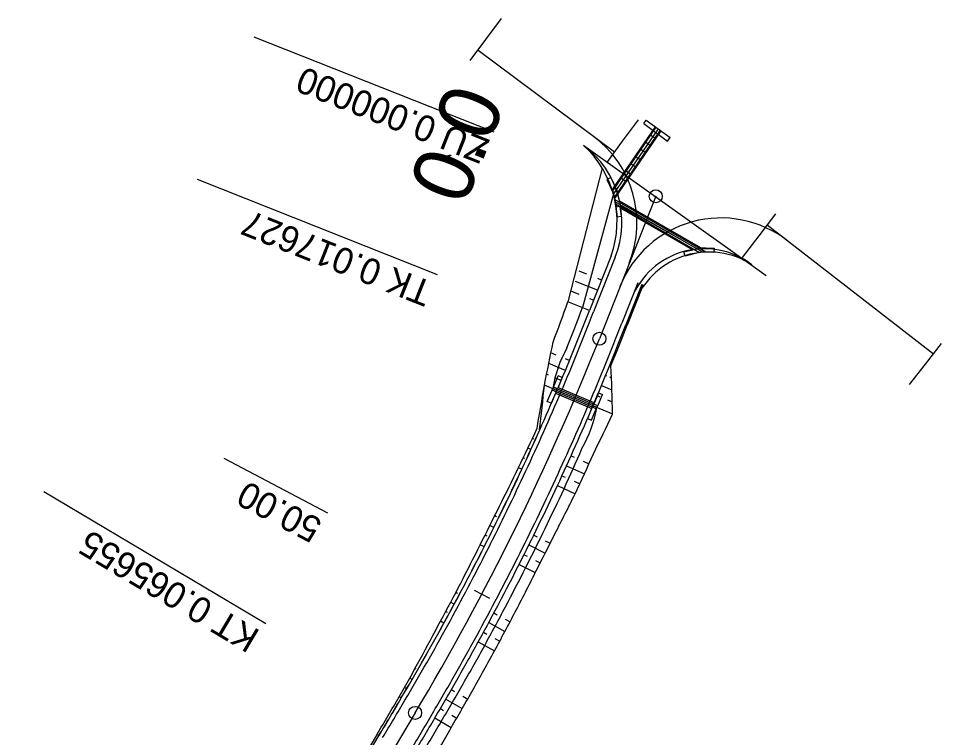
# Model space of a CAD drawing. Extents: x -481645 to -478728, y -1113199 to -1110710.
# Drawn here: x -479519.7 to -479413.6, y -1112428.2 to -1112345.5 of the extents above; entities that cross this region are included whole.
import ezdxf

# ---------------------------------------------------------------- set-up
doc = ezdxf.new("R2010")
doc.units = 0
for name, color, linetype in [('CP14_HRANA_TELESO', 7, 'Continuous'), ('CP14_KORUNA', 7, 'Continuous'), ('CP14_OSA', 7, 'Continuous'), ('CP14_PRIKOP', 7, 'Continuous'), ('CP14_STANICENI', 7, 'Continuous'), ('CP14_VOZOVKA', 7, 'Continuous'), ('CP14_ZPEVKRAJ', 7, 'Continuous'), ('CP1_HATCH_SLOPE_L', 7, 'Continuous'), ('CP1_HATCH_SLOPE_R', 7, 'Continuous'), ('CP1_HLBODY', 7, 'Continuous'), ('CP1_HRANA_TELESO', 7, 'Continuous'), ('CP1_OSA', 7, 'Continuous'), ('CP1_STANICENI', 7, 'Continuous'), ('CP1_VOZOVKA', 7, 'Continuous'), ('CP1_ZPEVKRAJ', 7, 'Continuous')]:
    doc.layers.add(name, color=color, linetype=linetype)

# ---------------------------------------------------------------- blocks, each defined once
blk = doc.blocks.new('A$C716')
at = {"layer": 'CP14_ZPEVKRAJ'}
for p, q in [((-5.015, 2.333), (-4.471, 3.623)), ((-4.01, 3.428), (-4.554, 2.138)), ((-4.01, 3.428), (-4.471, 3.623)), ((-5.17, 1.964), (-5.015, 2.333)), ((0, 0), (-5.093, 2.148)), ((-5.015, 2.333), (-0.383, 0.379)), ((-4.554, 2.138), (-5.015, 2.333)), ((-0.325, 0.517), (-4.496, 2.277)), ((-5.715, 0.674), (-5.17, 1.964)), ((-4.71, 1.77), (-5.254, 0.48)), ((-0.078, -0.184), (-5.171, 1.964)), ((-4.71, 1.77), (-5.17, 1.964)), ((-4.768, 1.632), (-0.597, -0.128)), ((0.161, 1.669), (-0.383, 0.379)), ((0.078, 0.184), (0.622, 1.474)), ((0.161, 1.669), (0.622, 1.474)), ((-5.254, 0.48), (-5.715, 0.674)), ((-0.538, 0.01), (-1.083, -1.28)), ((-0.078, -0.184), (-0.999, 0.204)), ((0.078, 0.184), (-0.844, 0.573)), ((-0.538, 0.01), (-0.383, 0.379)), ((-0.078, -0.184), (0.078, 0.184)), ((-0.622, -1.474), (-0.078, -0.184)), ((-1.083, -1.28), (-0.622, -1.474))]:
    blk.add_line(p, q, dxfattribs=at)

msp = doc.modelspace()

# ---------------------------------------------------------------- linework, layer by layer
at = {"layer": 'CP14_HRANA_TELESO'}
for p, q in [((-479448.47, -1112377.27), (-479448.47, -1112377.27)), ((-479448.4, -1112377.29), (-479448.34, -1112377.32)), ((-479448.93, -1112378.43), (-479448.8, -1112378.48)), ((-479449.39, -1112379.59), (-479449.39, -1112379.59)), ((-479449.32, -1112379.62), (-479449.26, -1112379.64)), ((-479449.85, -1112380.75), (-479449.72, -1112380.81)), ((-479452.19, -1112386.58), (-479452.08, -1112386.62)), ((-479451.75, -1112386.76), (-479451.52, -1112386.85)), ((-479452.67, -1112387.75), (-479451.47, -1112388.24)), ((-479453.15, -1112388.91), (-479452.85, -1112389.04)), ((-479451.98, -1112389.4), (-479451.43, -1112389.63)), ((-479453.64, -1112390.07), (-479451.39, -1112391.02)), ((-479456.17, -1112395.84), (-479455.8, -1112396)), ((-479454.77, -1112396.47), (-479454.11, -1112396.76)), ((-479456.69, -1112396.98), (-479454.63, -1112397.92)), ((-479457.21, -1112398.13), (-479456.83, -1112398.3)), ((-479455.81, -1112398.77), (-479455.16, -1112399.07)), ((-479457.74, -1112399.27), (-479455.7, -1112400.22)), ((-479460.45, -1112404.95), (-479460.08, -1112405.14)), ((-479461.01, -1112406.08), (-479459.13, -1112407.02)), ((-479459.13, -1112405.6), (-479458.56, -1112405.89)), ((-479461.57, -1112407.21), (-479461.2, -1112407.4)), ((-479462.14, -1112408.34), (-479460.28, -1112409.28)), ((-479460.26, -1112407.87), (-479459.7, -1112408.15)), ((-479465.04, -1112413.92), (-479464.67, -1112414.12)), ((-479463.74, -1112414.62), (-479463.17, -1112414.92)), ((-479465.63, -1112415.03), (-479463.77, -1112416.04)), ((-479466.23, -1112416.14), (-479465.86, -1112416.34)), ((-479464.93, -1112416.85), (-479464.36, -1112417.16)), ((-479466.84, -1112417.25), (-479464.97, -1112418.27)), ((-479469.92, -1112422.74), (-479469.56, -1112422.95)), ((-479470.55, -1112423.83), (-479468.67, -1112424.92)), ((-479468.62, -1112423.49), (-479468.04, -1112423.82)), ((-479471.19, -1112424.91), (-479470.83, -1112425.12)), ((-479471.83, -1112426), (-479469.95, -1112427.11)), ((-479469.89, -1112425.68), (-479469.31, -1112426.02))]:
    msp.add_line(p, q, dxfattribs=at)
at = {"layer": 'CP14_KORUNA'}
for p, q in [((-479447.81, -1112357.6), (-479447.51, -1112357.2)), ((-479447.81, -1112357.6), (-479445.08, -1112359.63)), ((-479447.51, -1112357.2), (-479444.78, -1112359.22)), ((-479446.48, -1112357.97), (-479451.45, -1112365.21)), ((-479446.4, -1112358.02), (-479451.41, -1112365.33)), ((-479446.16, -1112358.2), (-479451.3, -1112365.7)), ((-479445.92, -1112358.38), (-479451.21, -1112366.1)), ((-479445.84, -1112358.44), (-479451.18, -1112366.24)), ((-479447.58, -1112359.74), (-479447.08, -1112360.08)), ((-479447.01, -1112358.91), (-479446.52, -1112359.25)), ((-479445.08, -1112359.63), (-479444.78, -1112359.22)), ((-479448.14, -1112360.56), (-479447.65, -1112360.9)), ((-479448.14, -1112360.56), (-479447.65, -1112360.9)), ((-479448.14, -1112360.56), (-479447.65, -1112360.9)), ((-479448.14, -1112360.56), (-479447.65, -1112360.9)), ((-479448.14, -1112360.56), (-479447.65, -1112360.9)), ((-479448.14, -1112360.56), (-479447.65, -1112360.9)), ((-479448.14, -1112360.56), (-479447.65, -1112360.9)), ((-479448.14, -1112360.56), (-479447.65, -1112360.9)), ((-479448.71, -1112361.39), (-479448.21, -1112361.73)), ((-479449.27, -1112362.21), (-479448.78, -1112362.55)), ((-479451.58, -1112363.83), (-479452.04, -1112364.03)), ((-479451.58, -1112363.83), (-479451.03, -1112365.08)), ((-479450.48, -1112363.81), (-479449.83, -1112364.26)), ((-479449.84, -1112363.04), (-479449.34, -1112363.38)), ((-479452.04, -1112364.03), (-479451.3, -1112365.7)), ((-479451.3, -1112365.7), (-479450.95, -1112367.24)), ((-479450.92, -1112365.14), (-479450.47, -1112367.13)), ((-479450.47, -1112367.13), (-479450.95, -1112367.24))]:
    msp.add_line(p, q, dxfattribs=at)
at = {"layer": 'CP14_OSA'}
msp.add_circle((-479446.42, -1112365.98), 0.75, dxfattribs=at)
at = {"layer": 'CP14_PRIKOP'}
for p, q in [((-479454.36, -1112374.93), (-479455.23, -1112374.59)), ((-479452.66, -1112375.61), (-479453.08, -1112375.44)), ((-479453.12, -1112376.77), (-479455.66, -1112375.77)), ((-479455.24, -1112377.27), (-479456.09, -1112376.94)), ((-479453.58, -1112377.93), (-479453.99, -1112377.77)), ((-479454.04, -1112379.1), (-479456.52, -1112378.11)), ((-479457.88, -1112384.25), (-479458.48, -1112384)), ((-479456.82, -1112386.02), (-479458.72, -1112385.23)), ((-479456.35, -1112384.87), (-479456.82, -1112384.68)), ((-479458.77, -1112386.55), (-479458.97, -1112386.46)), ((-479457.3, -1112387.17), (-479457.94, -1112386.9)), ((-479457.79, -1112388.31), (-479459.23, -1112387.69)), ((-479460.44, -1112393.91), (-479460.6, -1112393.84)), ((-479460.27, -1112393.99), (-479460.28, -1112393.99)), ((-479460.78, -1112395.12), (-479461.13, -1112394.96)), ((-479461.48, -1112396.16), (-479461.66, -1112396.08)), ((-479461.3, -1112396.25), (-479461.3, -1112396.25)), ((-479461.82, -1112397.38), (-479462.2, -1112397.2)), ((-479464.72, -1112402.86), (-479464.94, -1112402.75)), ((-479464.49, -1112402.97), (-479464.5, -1112402.97)), ((-479465.04, -1112404.08), (-479465.49, -1112403.86)), ((-479465.83, -1112405.08), (-479466.05, -1112404.97)), ((-479465.59, -1112405.2), (-479465.6, -1112405.19)), ((-479466.15, -1112406.3), (-479466.61, -1112406.07)), ((-479469.23, -1112411.69), (-479469.43, -1112411.58)), ((-479469.6, -1112412.9), (-479470.01, -1112412.68)), ((-479469.01, -1112411.81), (-479469.02, -1112411.81)), ((-479470.39, -1112413.88), (-479470.59, -1112413.77)), ((-479470.78, -1112415.08), (-479471.18, -1112414.86)), ((-479470.19, -1112413.99), (-479470.19, -1112413.99)), ((-479473.97, -1112420.4), (-479474.12, -1112420.32)), ((-479473.82, -1112420.49), (-479473.83, -1112420.49)), ((-479474.44, -1112421.56), (-479474.72, -1112421.4)), ((-479475.21, -1112422.55), (-479475.33, -1112422.48)), ((-479475.07, -1112422.63), (-479475.07, -1112422.63)), ((-479475.7, -1112423.7), (-479475.95, -1112423.55))]:
    msp.add_line(p, q, dxfattribs=at)
at = {"layer": 'CP14_STANICENI'}
msp.add_line((-479454.71, -1112360.13), (-479433.74, -1112375.08), dxfattribs=at)
for centre, radius, start, end in [((-479461.31, -1112368.94), 11, 338.3823, 53.171), ((-479462.72, -1112368.87), 11.85, 340.5708, 47.4974), ((-479440.81, -1112381.01), 9, 52.7737, 158.3823), ((-479440.32, -1112381.56), 9.17, 57.3103, 156.3307)]:
    msp.add_arc(centre, radius, start, end, dxfattribs=at)
at = {"layer": 'CP14_VOZOVKA'}
for p, q in [((-479465.96, -1112347.94), (-479464.16, -1112345.52)), ((-479467.75, -1112350.37), (-479465.96, -1112347.94)), ((-479466.85, -1112349.16), (-479451.15, -1112360.88)), ((-479450.23, -1112359.65), (-479448.4, -1112357.17)), ((-479452.06, -1112362.12), (-479450.23, -1112359.65)), ((-479450.48, -1112367.03), (-479443.11, -1112371.16)), ((-479432.67, -1112368.01), (-479434.57, -1112370.51)), ((-479433.62, -1112369.26), (-479414.48, -1112384.1)), ((-479434.57, -1112370.51), (-479436.47, -1112373.01)), ((-479415.39, -1112385.28), (-479413.56, -1112382.92)), ((-479417.23, -1112387.63), (-479415.39, -1112385.28))]:
    msp.add_line(p, q, dxfattribs=at)
for centre, start, end in [((-479461.09, -1112369.06), 338.3823, 53.2576), ((-479438.92, -1112380.97), 52.2213, 158.3823)]:
    msp.add_arc(centre, 12.5, start, end, dxfattribs=at)
at = {"layer": 'CP14_ZPEVKRAJ'}
for p, q in [((-479450.92, -1112365.07), (-479451.41, -1112365.18)), ((-479451.41, -1112365.18), (-479451.09, -1112366.61)), ((-479450.56, -1112366.69), (-479450.92, -1112365.07)), ((-479441.4, -1112371.98), (-479451.15, -1112366.35)), ((-479451.09, -1112366.61), (-479450.87, -1112368.34)), ((-479441.1, -1112372.38), (-479451.09, -1112366.61)), ((-479451.05, -1112366.86), (-479441.38, -1112372.45)), ((-479450.6, -1112366.49), (-479441.28, -1112371.87)), ((-479450.38, -1112368.28), (-479450.51, -1112367.18)), ((-479442.21, -1112372.15), (-479450.49, -1112367.36)), ((-479450.87, -1112368.34), (-479450.38, -1112368.28)), ((-479443.18, -1112372.38), (-479442, -1112372.09)), ((-479443.05, -1112372.87), (-479443.18, -1112372.38)), ((-479441.1, -1112372.38), (-479443.05, -1112372.87)), ((-479441.62, -1112371.85), (-479439.71, -1112371.96)), ((-479440.65, -1112372.41), (-479441.4, -1112371.98)), ((-479439.74, -1112372.46), (-479441.1, -1112372.38)), ((-479439.71, -1112371.96), (-479439.74, -1112372.46))]:
    msp.add_line(p, q, dxfattribs=at)
at = {"layer": 'CP1_HATCH_SLOPE_L'}
for p, q in [((-479484.13, -1112402.43), (-479496.07, -1112396.14)), ((-479467.32, -1112411.29), (-479465.55, -1112412.23))]:
    msp.add_line(p, q, dxfattribs=at)
at = {"layer": 'CP1_HATCH_SLOPE_R'}
for p, q in [((-479465.01, -1112358.61), (-479492.62, -1112347.67)), ((-479471.51, -1112375), (-479499.12, -1112364.06)), ((-479491.28, -1112415.18), (-479516.79, -1112399.97))]:
    msp.add_line(p, q, dxfattribs=at)
for centre in [(-479446.42, -1112365.98), (-479452.91, -1112382.37), (-479474.1, -1112425.41)]:
    msp.add_circle(centre, 0.75, dxfattribs=at)
at = {"layer": 'CP1_HLBODY'}
for p, q in [((-479451.73, -1112374.63), (-479453.57, -1112379.28)), ((-479448.48, -1112375.92), (-479450.32, -1112380.57))]:
    msp.add_line(p, q, dxfattribs=at)
for centre, radius, start, end in [((-480285.69, -1112050.41), 894.75, 338.11546, 338.43476), ((-480292.19, -1112047.81), 905.25, 338.11578, 338.43312), ((-479731.81, -1112271.84), 298.25, 336.9742, 337.9291), ((-479731.81, -1112271.84), 301.75, 336.9742, 337.9291), ((-479731.81, -1112271.84), 298.25, 336.0193, 336.9742), ((-479731.81, -1112271.84), 301.75, 336.0193, 336.9742), ((-479731.81, -1112271.84), 298.25, 335.0643, 336.0193), ((-479731.81, -1112271.84), 301.75, 335.0643, 336.0193), ((-479731.81, -1112271.84), 298.25, 334.1094, 335.0643), ((-479731.81, -1112271.84), 301.75, 334.1094, 335.0643), ((-479731.81, -1112271.84), 298.25, 333.1545, 334.1094), ((-479731.81, -1112271.84), 301.75, 333.1545, 334.1094), ((-479731.81, -1112271.84), 298.25, 332.1995, 333.1545), ((-479731.81, -1112271.84), 301.75, 332.1995, 333.1545), ((-479731.81, -1112271.84), 298.25, 331.2446, 332.1995), ((-479731.81, -1112271.84), 301.75, 331.2446, 332.1995), ((-479731.81, -1112271.84), 298.25, 330.2897, 331.2446), ((-479731.81, -1112271.84), 301.75, 330.2897, 331.2446), ((-479731.81, -1112271.84), 298.25, 329.3347, 330.2897), ((-479731.81, -1112271.84), 301.75, 329.3347, 330.2897), ((-479604.65, -1112349.8), 149.12, 328.2579, 330.1776), ((-479603.14, -1112350.69), 150.88, 328.2677, 330.168)]:
    msp.add_arc(centre, radius, start, end, dxfattribs=at)
at = {"layer": 'CP1_HRANA_TELESO'}
for p, q in [((-479452.57, -1112362.76), (-479456.52, -1112378.11)), ((-479447.88, -1112376.16), (-479449.72, -1112380.81)), ((-479478.48, -1112427.86), (-479481.04, -1112432.16))]:
    msp.add_line(p, q, dxfattribs=at)
for centre, radius, start, end in [((-480288.38, -1112074.21), 885.64, 339.60985, 339.93096), ((-480293.42, -1112047.43), 907.18, 338.12203, 338.43901), ((-479748.53, -1112326.52), 295.7, 348.0615, 349.0346), ((-479754.84, -1112398.59), 303.55, 1.4283, 2.4777), ((-479752.3, -1112340.85), 296.79, 349.9355, 350.9194), ((-479727.22, -1112261.78), 304.61, 333.9376, 334.8932), ((-479729.9, -1112267.71), 297.37, 334.187, 335.142), ((-479731.4, -1112270.94), 304.51, 334.878, 335.8329), ((-479729.78, -1112267.64), 297.29, 333.21, 334.1651), ((-479728.52, -1112265.13), 304.43, 332.7023, 333.6575), ((-479731.36, -1112270.93), 297.24, 332.9573, 333.9123), ((-479730.73, -1112269.68), 304.35, 332.698, 333.6529), ((-479732.66, -1112273.5), 297.25, 332.5591, 333.514), ((-479732.53, -1112273.24), 304.35, 332.495, 333.4499), ((-479732.63, -1112273.38), 297.28, 331.5798, 332.5348), ((-479732.53, -1112273.18), 304.37, 331.5291, 332.484), ((-479734.58, -1112276.91), 297.34, 331.4025, 332.3576), ((-479732.62, -1112273.3), 304.4, 330.6036, 331.5586), ((-479733.87, -1112275.44), 297.43, 330.1327, 331.0878), ((-479732.62, -1112273.24), 304.42, 329.6373, 330.5923), ((-479605.41, -1112350.35), 148.73, 328.5897, 330.5138), ((-479602.42, -1112352.13), 152.22, 328.6037, 330.4895)]:
    msp.add_arc(centre, radius, start, end, dxfattribs=at)
at = {"layer": 'CP1_OSA'}
for p, q in [((-479446.42, -1112365.98), (-479452.91, -1112382.37)), ((-479474.1, -1112425.41), (-479519.71, -1112501.96))]:
    msp.add_line(p, q, dxfattribs=at)
msp.add_arc((-479731.81, -1112271.84), 300, 329.2096, 338.3823, dxfattribs=at)
at = {"layer": 'CP1_STANICENI'}
for p, q in [((-479451.08, -1112372.99), (-479453.57, -1112379.28)), ((-479448.48, -1112375.92), (-479450.32, -1112380.57))]:
    msp.add_line(p, q, dxfattribs=at)
for centre, radius, start, end in [((-480285.69, -1112050.41), 894.75, 338.11546, 338.43476), ((-480292.19, -1112047.81), 905.25, 338.11578, 338.43312), ((-479731.81, -1112271.84), 298.25, 336.9742, 337.9291), ((-479731.81, -1112271.84), 301.75, 336.9742, 337.9291), ((-479731.81, -1112271.84), 298.25, 336.0193, 336.9742), ((-479731.81, -1112271.84), 301.75, 336.0193, 336.9742), ((-479731.81, -1112271.84), 298.25, 335.0643, 336.0193), ((-479731.81, -1112271.84), 301.75, 335.0643, 336.0193), ((-479731.81, -1112271.84), 298.25, 334.1094, 335.0643), ((-479731.81, -1112271.84), 301.75, 334.1094, 335.0643), ((-479731.81, -1112271.84), 298.25, 333.1545, 334.1094), ((-479731.81, -1112271.84), 301.75, 333.1545, 334.1094), ((-479731.81, -1112271.84), 298.25, 332.1995, 333.1545), ((-479731.81, -1112271.84), 301.75, 332.1995, 333.1545), ((-479731.81, -1112271.84), 298.25, 331.2446, 332.1995), ((-479731.81, -1112271.84), 301.75, 331.2446, 332.1995), ((-479731.81, -1112271.84), 298.25, 330.2897, 331.2446), ((-479731.81, -1112271.84), 301.75, 330.2897, 331.2446), ((-479731.81, -1112271.84), 298.25, 329.3347, 330.2897), ((-479731.81, -1112271.84), 301.75, 329.3347, 330.2897), ((-479604.65, -1112349.8), 149.12, 328.2579, 330.1776), ((-479603.14, -1112350.69), 150.88, 328.2677, 330.168)]:
    msp.add_arc(centre, radius, start, end, dxfattribs=at)
at = {"layer": 'CP1_VOZOVKA'}
for p, q in [((-479451.54, -1112372.81), (-479454.04, -1112379.1)), ((-479448.01, -1112376.11), (-479449.85, -1112380.75)), ((-479478.26, -1112427.99), (-479480.82, -1112432.29))]:
    msp.add_line(p, q, dxfattribs=at)
for centre, radius, start, end in [((-480284.76, -1112050.78), 893.25, 338.11542, 338.43499), ((-480293.12, -1112047.44), 906.75, 338.11583, 338.43289), ((-479731.81, -1112271.84), 297.75, 336.9742, 337.9291), ((-479731.81, -1112271.84), 302.25, 336.9742, 337.9291), ((-479731.81, -1112271.84), 297.75, 336.0193, 336.9742), ((-479731.81, -1112271.84), 302.25, 336.0193, 336.9742), ((-479731.81, -1112271.84), 297.75, 335.0643, 336.0193), ((-479731.81, -1112271.84), 302.25, 335.0643, 336.0193), ((-479731.81, -1112271.84), 297.75, 334.1094, 335.0643), ((-479731.81, -1112271.84), 302.25, 334.1094, 335.0643), ((-479731.81, -1112271.84), 297.75, 333.1545, 334.1094), ((-479731.81, -1112271.84), 302.25, 333.1545, 334.1094), ((-479731.81, -1112271.84), 297.75, 332.1995, 333.1545), ((-479731.81, -1112271.84), 302.25, 332.1995, 333.1545), ((-479731.81, -1112271.84), 297.75, 331.2446, 332.1995), ((-479731.81, -1112271.84), 302.25, 331.2446, 332.1995), ((-479731.81, -1112271.84), 297.75, 330.2897, 331.2446), ((-479731.81, -1112271.84), 302.25, 330.2897, 331.2446), ((-479731.81, -1112271.84), 297.75, 329.3347, 330.2897), ((-479731.81, -1112271.84), 302.25, 329.3347, 330.2897), ((-479604.86, -1112349.67), 148.88, 328.2565, 330.179), ((-479602.93, -1112350.82), 151.12, 328.2691, 330.1666)]:
    msp.add_arc(centre, radius, start, end, dxfattribs=at)
at = {"layer": 'CP1_ZPEVKRAJ'}
for p, q in [((-479451.3, -1112365.7), (-479454.85, -1112378.78)), ((-479448, -1112376.11), (-479449.85, -1112380.76)), ((-479478.27, -1112427.99), (-479480.82, -1112432.28))]:
    msp.add_line(p, q, dxfattribs=at)
for centre, radius, start, end in [((-480286.21, -1112058.91), 890.78, 338.63608, 338.95613), ((-480293.14, -1112047.43), 906.78, 338.11583, 338.43288), ((-479444.56, -1112390.23), 13.87, 150.585, 171.1801), ((-479754.79, -1112358.91), 296.96, 353.4357, 354.4366), ((-479468.8, -1112387.22), 15.91, 330.6869, 348.9826), ((-479731.81, -1112271.84), 297.74, 335.0643, 336.0193), ((-479732.87, -1112274.2), 303.07, 335.5529, 336.5079), ((-479731.81, -1112271.84), 297.74, 334.1094, 335.0643), ((-479731.81, -1112271.84), 303.09, 334.1094, 335.0643), ((-479731.81, -1112271.84), 297.74, 333.1545, 334.1094), ((-479731.81, -1112271.84), 303.09, 333.1545, 334.1094), ((-479731.81, -1112271.84), 297.74, 332.1995, 333.1545), ((-479731.81, -1112271.84), 303.09, 332.1995, 333.1545), ((-479731.81, -1112271.84), 297.74, 331.2446, 332.1995), ((-479731.81, -1112271.84), 303.09, 331.2446, 332.1995), ((-479731.81, -1112271.84), 297.74, 330.2897, 331.2446), ((-479731.81, -1112271.84), 303.09, 330.2897, 331.2446), ((-479731.81, -1112271.84), 297.74, 329.3347, 330.2897), ((-479731.81, -1112271.84), 303.09, 329.3347, 330.2897), ((-479604.87, -1112349.67), 148.87, 328.2565, 330.179), ((-479602.57, -1112351.03), 151.54, 328.2714, 330.1644)]:
    msp.add_arc(centre, radius, start, end, dxfattribs=at)

# ---------------------------------------------------------------- block references
at = {"layer": 'CP14_ZPEVKRAJ'}
msp.add_blockref('A$C716', (-479453.18, -1112390.26), dxfattribs=at)

# ---------------------------------------------------------------- texts
at = {"layer": 'CP14_OSA'}
msp.add_text('0.0', height=7, rotation=68.3367, dxfattribs=at).set_placement((-479468.45, -1112367.27))
at = {"layer": 'CP1_HATCH_SLOPE_L'}
msp.add_text('50.00', height=3, rotation=152.1995, dxfattribs=at).set_placement((-479484.6, -1112403.32))
at = {"layer": 'CP1_HATCH_SLOPE_R'}
for s, rotation, p in [('ZÚ 0.000000', 158.3823, (-479465.38, -1112359.54)), ('TK 0.017627', 158.3823, (-479471.88, -1112375.93)), ('KT 0.065655', 149.2096, (-479491.79, -1112416.03))]:
    msp.add_text(s, height=3, rotation=rotation, dxfattribs=at).set_placement(p)

doc.saveas('drawing.dxf')
